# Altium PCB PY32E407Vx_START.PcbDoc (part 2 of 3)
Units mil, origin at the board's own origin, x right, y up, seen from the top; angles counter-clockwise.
Board outline 5249.65 x 2929.09 mil, 4 copper layers (Top Layer, GND, POWER, Bottom Layer); 239 components, 235 nets, 934 pads, 637 vias.
Unrouted connection lines stored in the file: 84.
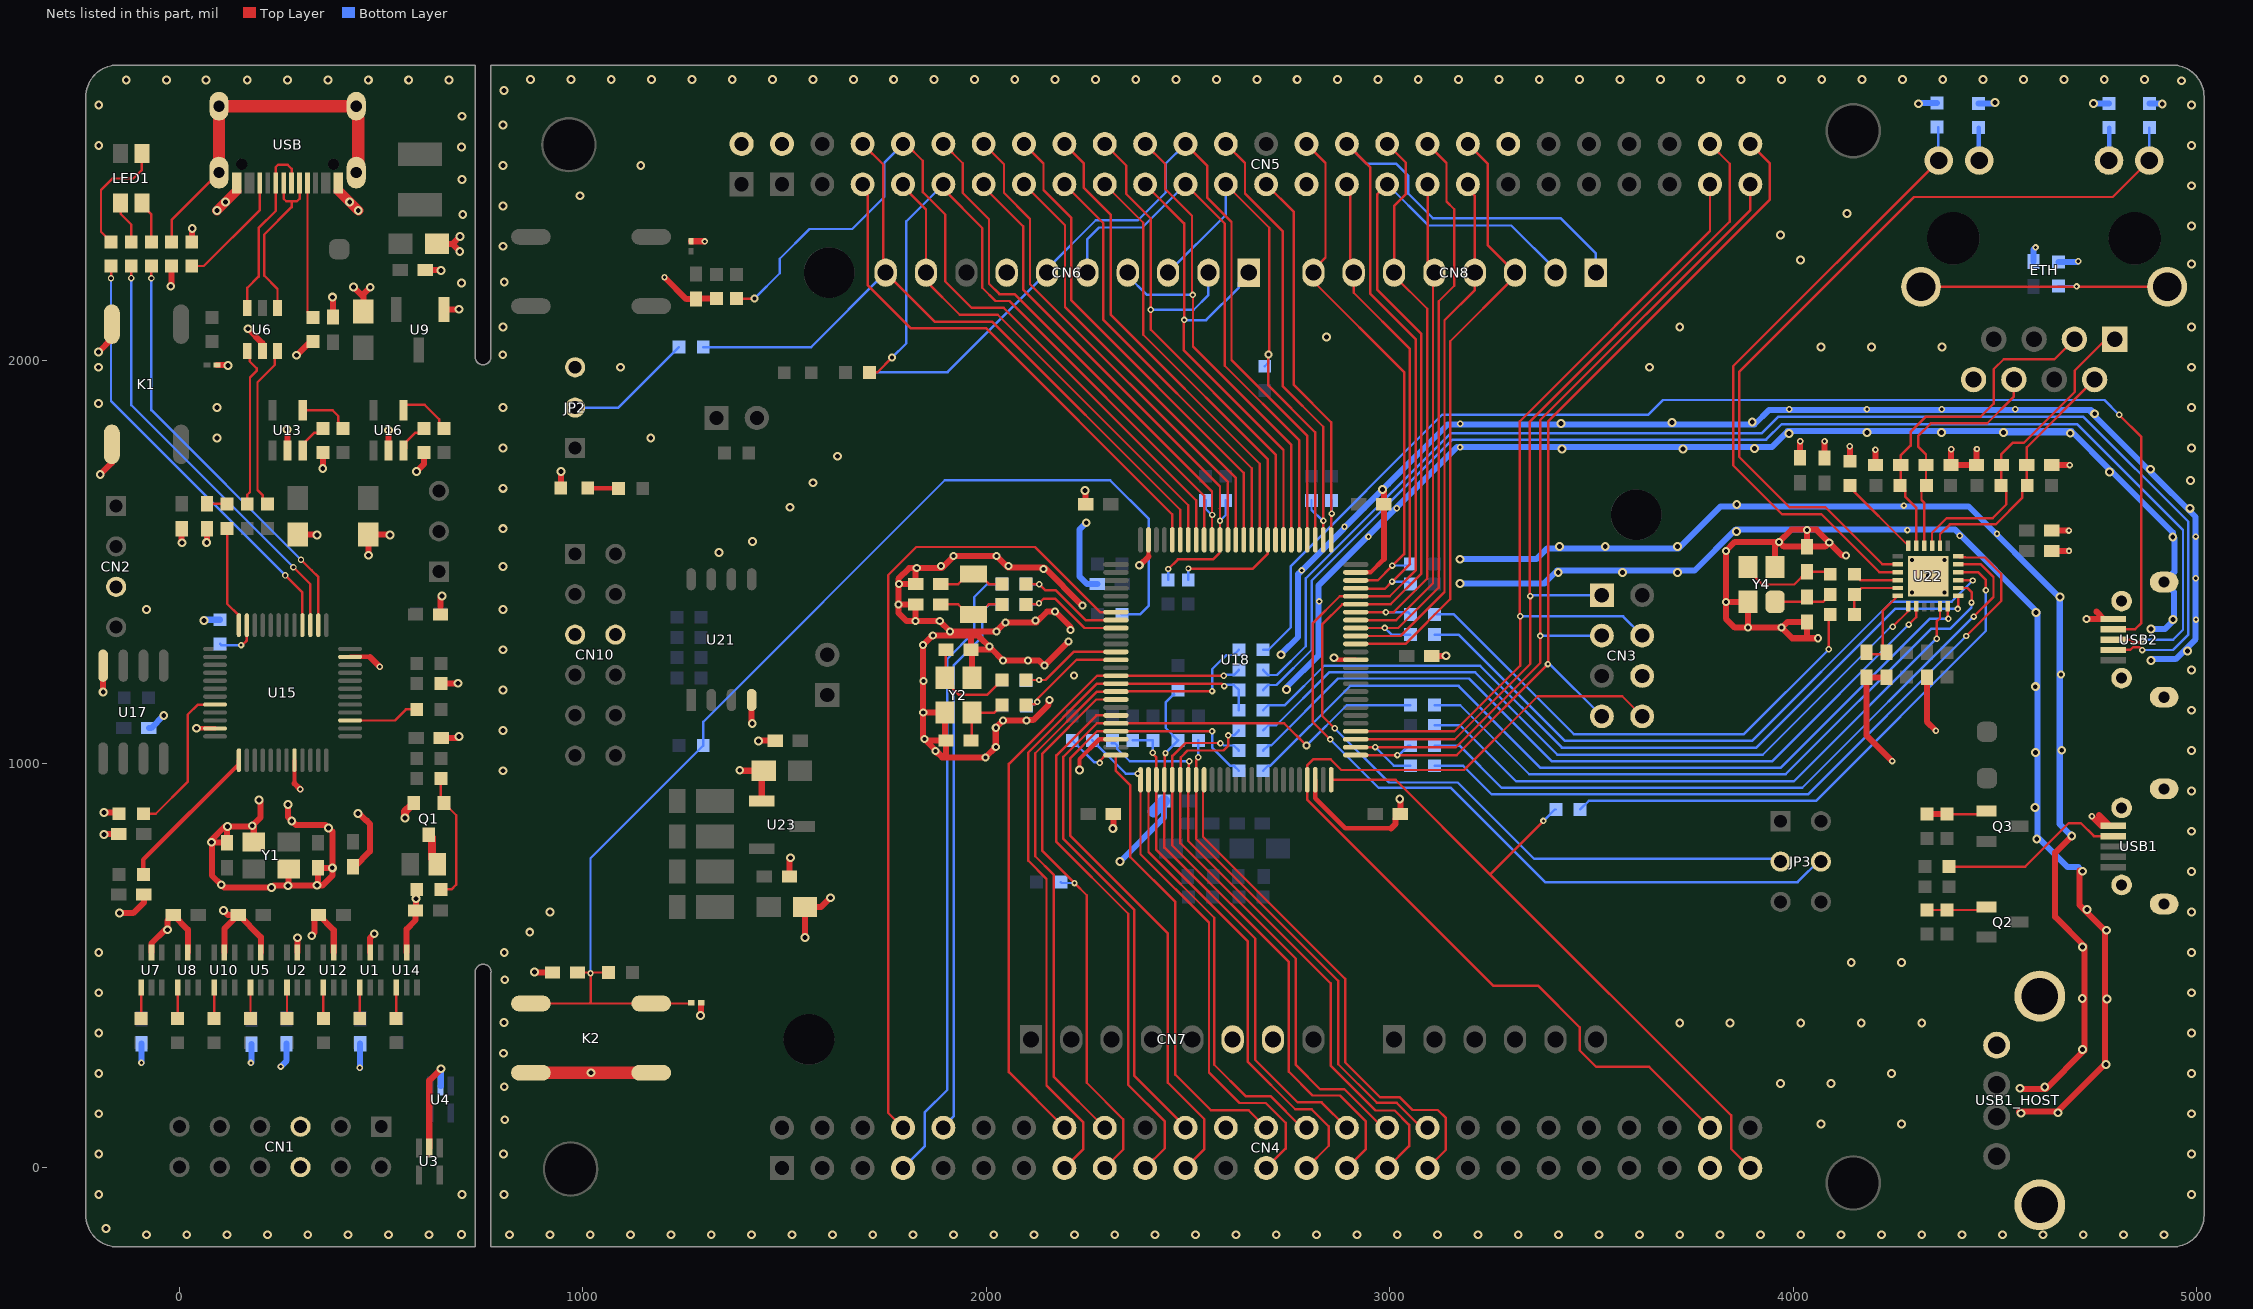
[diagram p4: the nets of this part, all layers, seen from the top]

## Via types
v1: diameter 22, hole 12, Top Layer to Bottom Layer, tented both sides, 398 vias
v2: diameter 16, hole 8, Top Layer to Bottom Layer, tented both sides, 111 vias
v3: diameter 20, hole 10, Top Layer to Bottom Layer, tented both sides, 54 vias
v4: diameter 16, hole 9, Top Layer to Bottom Layer, tented both sides, 41 vias
v5: diameter 30, hole 15, Top Layer to Bottom Layer, tented both sides, 15 vias
v6: diameter 20, hole 10, Top Layer to Bottom Layer, 9 vias
v7: diameter 15, hole 8, Top Layer to Bottom Layer, tented both sides, 5 vias
v8: diameter 16, hole 8, Top Layer to Bottom Layer, 3 vias
v9: diameter 20, hole 12, Top Layer to Bottom Layer, tented both sides, 1 vias

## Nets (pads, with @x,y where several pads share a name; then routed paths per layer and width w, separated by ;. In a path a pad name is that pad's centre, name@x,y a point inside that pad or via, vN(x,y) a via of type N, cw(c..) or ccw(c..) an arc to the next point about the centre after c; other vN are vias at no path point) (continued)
GND: C1.1 C2.1 C3.1 C4.1 C5.1 C6.1 C7.1 C8.1 C9.1 C10.1 C11.1 C12.1 C13.1 C14.1 C15.1 C16.1 C17.1 C18.1 C19.1 C20.1 C21.1 C22.1 C23.1 C24.1 C25.1 C26.1 C27.1 C28.1 C29.1 C30.1 C31.1 C32.1 C33.1 C34.1 C39.1 C40.1 C41.1 C42.1 C43.1 C44.1 C45.1 C46.1 C47.1 C48.1 C49.1 C50.2 C51.1 C52.1 C53.1 C54.1 C55.1 C56.1 C57.1 C58.1 CN1.5 CN1.6 CN2.3 CN3.6 CN4.24 CN4.47 CN5.2 CN5.27 CN5.38 CN6.7 CN7.6 CN7.7 CN10.5 CN10.6 CN11.2 ETH.8 JP2.3 K1.1 K2.2 L4.1 LED3.2 Q1.2 R1.1 R3.2 R7.2 R19.1 R20.1 R25.1 R27.2 R29.1 R32.2 R78.2 R82.1 R102.2 R103.1 R104.1 R106.1 R109.1 U1.2 U2.2 U3.2 U4.2 U5.2 U6.2 U7.2 U8.2 U9.1 U10.2 U11.2 U12.2 U13.2 U14.2 U15.8 U15.23 U15.47 U16.2 U17.4 U18.23 U18.48 U18.63 U18.74 U18.99 U19.2 U20.2 U21.4 U22.25 U23.1 USB1.5 USB1.6 USB1.7 USB1.8 USB1.9 USB1_HOST.4 USB1_HOST.5 USB2.5 USB2.6 USB2.7 USB2.8 USB2.9 USB.A1 USB.A12 USB.B1 USB.B12 Y1.2 Y1.4 Y2.2 Y2.4 Y4.2 Y4.4 | length 25027.6
  Top Layer w11: v1@42.64,1087.25 U15.47@88.04,1087.25 ; 285.03,950.62 U15.8@285.03,1008.18 ; U15.23@422.82,1264.27 472.02,1264.27 ; v1(2230.48,983.64) 2230.48,1011.16 2279.56,1060.24 U18.23@2320.76,1060.24 ; 2401.46,1512.92 U18.99@2401.46,1554.33 ; U18.48@2814.85,959.85 2814.85,913.94 2889.41,839.39 3002.73,839.39 ; v1(2860.83,1262.2) 2863.8,1262.2 2868.91,1257.09 U18.63@2915.24,1257.09 ; U18.74@2915.24,1473.63 2951.64,1473.63 2984.6,1506.59
  Top Layer w15: v1(-200.6,2020) -167.7,2052.9 K1.1@-167.7,2089 ; v1(-196.4,1716.6) -167.7,1745.3 K1.1@-167.7,1791 ; U17.4@-189.3,1242.5 -189.3,1177.2 v1(-189.1,1177) ; v1(-187.5,824.4) -186.4,825.5 C22.1@-150.5,825.5 ; v1(-186.8,879.1) -153.1,879.1 R27.2@-149.5,875.5 ; v1(-148.9,629.19) -114.8,629.19 -88.5,655.49 C20.1@-88.5,675.5 ; U7.2@-69.37,531.35 -69.37,554.39 -35.78,587.99 v1(-30,587.99) -30,610.6 C9.1@-15.7,624.9 20.97,588.23 U8.2@20.97,531.35 ; v1(-21.5,2182.89) -19.5,2184.89 R7.2@-19.5,2233 ; C5.1@5.5,1582 5.5,1548.19 v1(6.5,1547.19) ; R3.2@30.5,2293 30.5,2325.09 v1(31.6,2326.19) ; v1(42.5,1087.39) v1@42.64,1087.25 ; v1(67.41,1548.02) 68,1548.62 C16.1@68,1582 ; v1(79.73,804.88) 78.34,806.27 78.34,809.58 112.86,844.09 v1(119,844.09) 180,844.09 180.31,844.41 v1(180.31,845.73) 201.11,866.53 ; U11.2@92.8,1988 118.8,1988 v1(119.9,1986.9) ; v1(109.46,635.54) 120.09,624.9 C7.1@145.6,624.9 ; U10.2@111.31,531.35 111.31,590.61 C7.1@145.6,624.9 ; v1@118,843.09 C18.1@118,803.6 116.72,804.88 80.6,804.88 80.6,722.34 v1(103.41,699.53) 110.12,692.82 v1(228,692.82) 233.02,697.85 v1@340.42,697.85 ; USB.A12@141.34,2424.38 USB.A12@141.34,2454.43 ; v1(169.57,2077.44) 169.86,2077.44 205.5,2041.81 U6.2@205.5,2022.35 ; Y1.2@183.99,806.07 v1@183.99,842.05 ; v1(196.93,909.29) 200.79,905.43 200.79,866.85 ; U5.2@201.66,531.35 201.66,569.94 146.7,624.9 C7.1@145.6,624.9 ; v1(266.8,1827.9) 268,1826.7 U13.2@268,1775.5 ; v1(269.05,898.67) v1@269.3,898.92 ; v1@269.3,898.67 269.3,867.02 288.22,848.09 361.61,848.09 378.78,830.92 v1(378.78,741.6) ; v1@270.61,698.7 Y1.4@270.61,739.14 ; 285.03,950.62 v4(299.69,935.96) ; v1(290.2,2012) 323.7,2045.5 R1.1@330.5,2045.5 ; U2.2@292,531.35 292.07,531.42 292.07,567.82 v1(292.43,568.19) ; C6.1@293,1568 339.4,1568 v1(340.6,1566.8) ; v1(327.92,573.23) 327.92,575.12 334.56,581.76 334.56,622.22 337.24,624.9 C10.1@344.5,624.9 382.34,587.06 U12.2@382.34,531.35 ; v1(340.97,698.4) 354.87,698.4 378.78,722.31 v1(378.78,741.6) ; v1@343,700.43 C23.1@343,741.6 v1(378.78,741.6) ; v1(355.1,1731.5) 355.5,1731.9 R25.1@355.5,1770.5 ; v1(379.4,2155.8) 380.5,2154.7 C2.1@380.5,2106.5 ; USB.A1@394.32,2423.59 USB.A1@394.32,2454.49 ; C21.1@430.5,744.5 434.17,744.5 471.88,782.21 471.88,850.71 464.1,858.49 463.14,858.49 445.76,875.87 v1(442.78,875.87) ; v1(430.9,2181.4) 455.5,2156.8 ; C1.1@455.5,2120.5 455.5,2156.8 ; v1(468.62,1516.3) 468,1516.92 C15.1@468,1568 519.89,1568 v1(521.6,1566.29) ; 472.02,1264.27 v4(496.57,1239.72) ; U1.2@472.69,531.35 472.69,568.03 v1(482.82,578.16) ; v1(472.7,2180.4) 455.5,2163.2 455.5,2156.8 ; v1(517.6,1825.9) 518,1825.5 U16.2@518,1775.5 ; U14.2@563.03,531.35 563.03,589.77 585,611.74 C8.1@585,636.09 586,637.09 v1(586,665.09) 588,667.09 R19.1@588,688 ; Q1.2@573.6,895.37 Q1.2@580.6,902.37 ; v1(587.6,1723.94) 605.5,1741.84 R29.1@605.5,1770.5 ; C4.1@609.1,2223.2 646.7,2223.2 v1(647.8,2222.1) ; U3.2@619,47.46 619,214.18 v1(648.39,243.57) ; C3.1@638,2288 675.69,2288 ; C19.1@647,1369.3 647,1411.19 v1(650.8,1414.99) ; R20.1@648,1198 688.91,1198 v1(690,1199.09) ; C24.1@649,1063 689.21,1063 v1(693.1,1066.89) ; U9.1@655.5,2125.5 692.01,2125.5 v1(692.4,2125.89) ; v1(694.5,2269.19) 675.69,2288 ; v1(694.9,2306.09) 676.81,2288 675.69,2288 ; v1(879.9,482.99) 880.8,482.09 C29.1@924.5,482.09 ; LED3.2@945,1683.09 945,1723.19 v1(945.5,1723.69) ; v2(1202,2205.09) 1256,2151.09 C39.1@1280.5,2151.09 1281.5,2152.09 R82.1@1330.5,2152.09 ; U20.2@1268,2294.4 1301.1,2294.4 v2(1301.55,2293.94) ; v1(1291.5,375.24) 1292.8,376.54 U19.2@1292.8,407.09 ; v1(1388.5,983.39) 1389.8,982.09 C55.1@1448,982.09 1443,977.09 U23.1@1443,907.09 ; U21.4@1418,1157.49 1418,1100.59 v1(1419.4,1099.19) ; v1(1434.7,1055.49) 1435.8,1056.59 C56.1@1476.4,1056.59 ; C57.1@1511.6,720.29 1511.6,763.79 v1(1514.4,766.59) ; v1(1550.34,569.03) 1550.5,569.19 C54.1@1550.5,644.59 1590.3,644.59 v1(1613.21,667.51) ; v3@1781.7,1395.19 v3(1782.3,1394.59) C28.1@1824.5,1394.59 v3(1824.5,1353.19) v3@1824.6,1353.09 ; v3(1782.7,1444.59) C27.1@1824.5,1444.59 1824.5,1481.79 v3(1827.2,1484.49) ; v3(1843.29,1126.28) Y2.4@1897.03,1126.28 1897.03,1057.09 v3@1849.7,1057.09 ; v3(1873.6,1030.69) 1879.11,1025.19 1880.26,1025.19 1890.15,1015.29 1891.5,1015.29 ; C26.1@1899.5,1057.09 1899.5,1015.79 1900,1015.29 ; 1961.5,1316.59 C25.1@1961.5,1282.09 ; Y2.2@1963.96,1212.9 1963.96,1279.63 C25.1@1961.5,1282.09 ; v3(2007,1290.49) 2007,1289.59 v3@2012.8,1283.79 ; v3@2098.7,1106.39 v3(2040.7,1106.39) v3(2023,1088.69) v3(2023,1040.79) v3(1997.5,1015.29) 1891.5,1015.29 ; v3@2099.68,1107.78 2115.68,1107.78 2153.78,1145.88 2153.78,1154.94 v3(2156.6,1157.76) v3@2158.2,1157.76 ; v3(2203.4,1302.59) v3(2143.3,1242.49) 2129.9,1255.89 v3(2102.4,1255.89) v3(2040.7,1255.89) v3@2012.8,1283.79 ; v3(2208.6,1331.19) 2208.6,1338.49 v3(2170.2,1376.89) 2150.4,1376.89 2123.35,1349.85 v3(2046.85,1349.85) v3(2024.7,1327.69) v3(1909.6,1327.69) v3(1884.2,1353.09) v3@1824.6,1353.09 ; v3(2237.6,1391.29) 2142.7,1486.19 2053,1486.19 v3(2025.2,1513.99) v3(1918.38,1513.99) 1888.88,1484.49 v3(1827.2,1484.49) ; v1(2244.3,1676.89) 2245.7,1675.49 C34.1@2245.7,1642.49 ; v1(2313.1,839.19) 2314.54,840.63 C32.1@2314.54,875.01 ; v1(2378.76,1491.31) 2379.86,1491.31 2401.46,1512.92 ; v1(2981.33,1679.59) 2984.6,1676.31 C33.1@2984.6,1642.49 2984.6,1506.59 ; 3002.73,839.39 3014.15,850.81 3014.15,863.55 C31.1@3025.61,875.01 ; v1(3024.2,912.19) 3025.61,910.78 C31.1@3025.61,878.2 ; C30.1@3103.8,1266.29 3137.94,1266.29 v1(3138.8,1267.16) ; v3(3832.9,1400.79) Y4.4@3887.53,1400.79 3887.53,1337.13 v3(3887.1,1336.7) ; Y4.2@3954.46,1487.4 3954.46,1539.36 v3(3964.41,1549.3) ; C48.1@4016.2,1757.89 4016.2,1798.49 v2(4016.7,1798.99) ; 4033.5,1315.04 C51.1@4033.5,1350.59 3984.59,1350.59 v3(3970.7,1336.7) ; v3(4033.5,1578.79) C50.2@4033.5,1537.59 ; v3(4061,1310.49) 3996.9,1310.49 v3(3970.7,1336.7) ; C47.1@4076.7,1757.19 4076.7,1798.29 v2(4076.9,1798.49) ; v3(4088.65,1547.64) 4078.6,1537.59 C50.2@4033.5,1537.59 ; v3(4130.2,1515.39) 4120.9,1515.39 4056.4,1579.89 3995,1579.89 v3(3964.41,1549.3) ; v2(4139.5,1786.29) 4139.7,1786.09 R102.2@4139.7,1749.09 ; v2(4203.1,1777.59) 4203.4,1777.29 C41.1@4203.4,1739.59 ; C53.1@4230.5,1213.59 C52.1@4180.5,1213.59 4180.5,1070.09 v2(4244.5,1006.09) ; C49.1@4330.5,1213.59 4330.5,1103.79 v2(4353.1,1081.19) ; v2(4391.2,1778.89) 4390.4,1778.09 C42.1@4390.4,1739.59 C43.1@4453.4,1739.59 4453.4,1778.39 v2(4454.5,1779.49) ; v1@4558.7,137.29 4654.1,137.29 4771.91,255.1 4771.91,586.39 4709.26,649.04 4709.26,734.45 4714.88,734.45 v1(4716.11,733.22) ; v1@4560.6,193.19 4625.05,193.19 4720.9,289.05 4720.9,547.89 4648.6,620.19 4648.6,779.13 v1(4689.69,820.22) ; C45.1@4640,1527.09 4682.58,1527.09 v2(4682.74,1526.86) v2(4682.74,1526.86) ; C46.1@4640,1577.09 4682.44,1577.09 v2(4682.72,1577.37) ; C44.1@4640.4,1739.59 4640.5,1739.69 v2(4684.5,1739.69) ; v6(4726,1357.99) 4726.12,1357.99 4726.4,1358.27 USB2.5@4792.65,1358.27 4769.02,1358.27 4751.15,1376.15 ; v2(4739.5,869.39) 4763.12,845.77 USB1.5@4783.82,845.77 ; 4757.6,871.99 USB1.5@4783.82,845.77 ; USB1.5@4792.65,845.77 USB1.5@4783.82,845.77 ; v3@1824.6,1353.09 1802.3,1353.09 1781.7,1373.69 1781.7,1457.79 1808.4,1484.49 v3(1827.2,1484.49) ; v3@1849.7,1057.09 1843,1063.79 v3(1843,1293.89) v3(1866.9,1317.79) 1978.8,1317.79 v3@2012.8,1283.79 ; v3@1849.7,1057.09 1891.5,1015.29 ; C25.1@1961.5,1282.09 2011.1,1282.09 v3@2012.8,1283.79 ; v3(3964.41,1549.3) 3976.12,1537.59 C50.2@4033.5,1537.59 ; v3(3964.41,1549.3) 3854.89,1549.3 v3(3832.39,1526.8) 3832.39,1359.01 3854.7,1336.7 v3(3970.7,1336.7)
  Top Layer w20: v1(559.11,864.91) 559.11,880.88 Q1.2@573.6,895.37
  Top Layer w25: v1(92.86,2370.4) v1(114.23,2391.77) USB.A12@141.38,2418.92 ; USB.A1@394.62,2418.92 v1(421.77,2391.77) v1(443.14,2370.4)
  Top Layer w30: K2.2@871,233.59 K2.2@1169,233.59
  Bottom Layer w15: C12.1@-94.3,305.6 v2(-94.3,258.39) v2@-94,258.09 ; C17.1@-76,1088 -70.1,1088 v1(-38.9,1119.2) ; v1(61.1,1354.39) 63.1,1356.39 R32.2@100.8,1356.39 ; v2(177,258.09) 178.2,259.29 C13.1@178.2,304.3 ; v2(251,249.09) 265.7,263.79 C11.1@265.7,305.7 ; v2(447,246.09) 447.9,246.99 C14.1@447.9,305.7 ; U4.2@647,200.46 647.7,201.16 647.7,242.87 v1(648.39,243.57) ; v1(2247.1,1596.79) 2230.1,1579.79 2230.1,1464.19 2249.7,1444.59 C58.1@2274.5,1444.59 ; v1(2330.8,756.95) 2440.4,866.55 R78.2@2440.4,907.19 ; v1(2730.3,1269.49) 2730.3,1271.79 2772.11,1313.6 2772.11,1469.41 2774.8,1472.09 2996.09,1693.38 ; v1(2743.43,1183.82) 2743.43,1188.93 2823.22,1268.72 2823.22,1441.62 3166.55,1784.95 3946.85,1784.95 3985.62,1823.71 v1@4688.98,1823.71 ; v1(2981.33,1679.59) 2982.29,1679.59 2996.09,1693.38 ; v1(3173.2,1446.49) 3382.5,1446.49 3414.5,1478.49 3755,1478.49 3857,1580.49 4399.6,1580.49 v1@4604.5,1375.59 ; v1(3173.2,1506.39) 3362.61,1506.39 3389.01,1532.79 3714.9,1532.79 3819.3,1637.19 4433.7,1637.19 4659.9,1410.99 4659.9,850.3 4661.37,848.83 4661.37,848.42 4689.58,820.22 v1(4689.69,820.22) 4686.88,823.03 v1@4686.88,824.84 ; v1(4309.48,2635.12) 4311.46,2637.09 R104.1@4355.5,2637.09 ; R106.1@4459,2636.09 4497.36,2636.09 v1(4499.61,2638.34) ; v1(4520.38,1820.15) 4685.42,1820.15 v1@4688.98,1823.71 ; C40.1@4594.5,2244.09 4594.5,2273.59 v2(4600,2279.09) ; v1(4600.86,1374.3) 4603.2,1374.3 v1@4604.5,1375.59 ; L4.1@4657,2243.09 4704,2243.09 v2(4705.5,2244.59) ; v1(4716.11,733.22) 4706.08,743.25 4679.74,743.25 4604.5,818.49 4604.5,890.77 4604.5,1032.22 4604.5,1190.49 v1@4604.5,1375.59 ; v1(4743.69,2636.07) R109.1@4782,2636.09 ; v1(4746.43,1866.91) 4736.63,1876.71 4731.08,1876.71 ; v1(4783.11,1722.47) 4789.94,1722.47 4939.87,1572.55 v1(4939.87,1561.82) 4943.3,1558.38 4943.7,1558.38 4943.7,1475.15 USB2.7@4918.35,1449.8 4942.78,1425.37 4942.78,1359.02 v1(4940.65,1356.89) ; v1@4786.67,1726.03 v1@4688.98,1823.71 ; R103.1@4882,2636.09 4912.44,2636.09 v1(4913.76,2634.78) ; v1(4884.42,1729.44) 4884.42,1723.37 4996.8,1610.99 ; v1(4886.1,1255.3) 4889.43,1258.64 4947.18,1258.64 4996.8,1308.26 4996.8,1610.99 ; v1@4888.51,1330.89 v1(4886.1,1333.29) 4920.41,1333.29 v1@4940.65,1353.53 ; 2996.09,1693.38 3143.03,1840.33 3903.43,1840.33 3939.82,1876.71 4731.08,1876.71 ; 4731.08,1876.71 4996.8,1610.99
  Bottom Layer w30: 2414.4,881.19 R78.2@2440.4,907.19
  other v1: -82,-167.91 18,-167.91 118,-167.91 218,-167.91 318,-167.91 418,-167.91 518,-167.91 618,-167.91 818,-167.91 918,-167.91 1018,-167.91 1118,-167.91 1218,-167.91 1318,-167.91 1418,-167.91 1518,-167.91 1618,-167.91 1718,-167.91 1818,-167.91 1918,-167.91 2018,-167.91 2118,-167.91 2218,-167.91 2318,-167.91 2418,-167.91 2518,-167.91 2618,-167.91 2718,-167.91 2818,-167.91 2918,-167.91 3018,-167.91 3118,-167.91 3218,-167.91 3318,-167.91 3418,-167.91 3518,-167.91 3618,-167.91 3718,-167.91 3818,-167.91 3918,-167.91 4018,-167.91 4118,-167.91 4218,-167.91 4318,-167.91 4418,-167.91 4518,-167.91 4618,-167.91 4718,-167.91 4818,-167.91 4918,-167.91 699,-166.91 -182,-151.91 -200,-67.91 700,-67.91 804,-67.91 4986,-67.91 -200,32.09 803,32.09 4986,32.09 4068,107.09 4268,107.09 806,117.09 -200,132.09 4986,132.09 4564.07,133.4 4655.66,134.66 4561.61,195.4 4622.77,198.53 805,199.09 3968,207.09 4093,207.09 -200,232.09 4243,232.09 4986,232.09 1020,233.59 4774.65,253.93 803,282.09 4715.92,291.09 -200,332.09 4986,332.09 3718,357.09 3843,357.09 4018,357.09 4168,357.09 4318,357.09 804,358.09 4777.1,416.27 4715.62,417.47 -200,432.09 4986,432.09 806,464.09 4143,507.09 4268,507.09 -200,532.09 805,532.09 4986,532.09 4715.94,545.57 868,582.09 4775.74,586.97 918,632.09 4986,632.09 4727.01,638.57 269,697.09 4986,732.09 4602.84,813.23 4986,832.09 369.17,840.53 278.29,858.03 4598.86,890.77 4986,932.09 802,982.09 4600,1027.09 4986,1032.09 4664.91,1033.05 802,1082.09 4986,1132.09 802,1182.09 4599.3,1190.49 4986,1232.09 4976.16,1279.08 802,1282.09 -82,1382.09 802,1382.09 4660.78,1412.8 3417.12,1473.15 3576.08,1473.33 3712.6,1473.53 802,1488.09 1336.8,1522.89 3420.44,1538.04 3533.62,1537.99 3712.45,1537.97 1420.1,1550.69 3859.03,1575.43 802,1582.09 4982.77,1632.55 1512.8,1635.09 3859.49,1641.92 802,1682.09 1570.1,1695.99 4983.9,1701.29 1630.4,1761.59 3426.61,1779.85 3726.4,1779.79 3903.69,1780.4 802,1782.09 4986,1782.09 93,1807.09 1168,1807.09 3988.62,1817.95 4685.9,1818.65 4182.4,1820.15 4366.6,1820.15 3424.17,1843.05 3698.7,1844.89 3897.7,1846.79 93,1882.09 802,1882.09 4986,1882.09 -201,1892.09 -201,1982.09 1093,1982.09 3643,1982.09 4986,1982.09 801,2013.09 4068,2032.09 4193,2032.09 4368,2032.09 2843,2057.09 802,2082.09 3718,2082.09 4986,2082.09 699,2191.09 805,2193.09 4986,2238.09 4017,2248.09 802,2282.09 3968,2310.09 4986,2332.09 702,2361.09 4133,2363.09 802,2382.09 993,2407.09 4986,2432.09 700,2447.09 802,2482.09 1143,2482.09 699,2528.09 -200,2532.09 4986,2532.09 802,2582.09 700,2604.09 -200,2632.09 4986,2632.09 804,2668.09 4962,2692.09 -132,2694.09 -32,2694.09 66,2694.09 168,2694.09 268,2694.09 368,2694.09 468,2694.09 568,2694.09 668,2694.09 870,2695.09 970,2695.09 1070,2695.09 1170,2695.09 1270,2695.09 1370,2695.09 1470,2695.09 1570,2695.09 1670,2695.09 1770,2695.09 1870,2695.09 1970,2695.09 2070,2695.09 2170,2695.09 2270,2695.09 2370,2695.09 2470,2695.09 2570,2695.09 2670,2695.09 2770,2695.09 2870,2695.09 2970,2695.09 3070,2695.09 3170,2695.09 3270,2695.09 3370,2695.09 3470,2695.09 3570,2695.09 3670,2695.09 3770,2695.09 3870,2695.09 3970,2695.09 4070,2695.09 4170,2695.09 4270,2695.09 4370,2695.09 4470,2695.09 4570,2695.09 4670,2695.09 4770,2695.09 4870,2695.09
  other v2: 2824.77,1401.74 2781.04,1478.69 2946.41,1562.33 4412.1,1564.79 4504.4,1569.69 4282.3,1578.59 2887.21,1586.96 3016.87,1632.8 4273.8,1639.19 3173.63,1783.63 3174.39,1841.92 4182,1877.79 4549.5,1877.79 3989.3,1878.09 4367.6,1877.99
  other v3: 1846.35,1060.44 2098.7,1106.79 1843.4,1204.29 2216.94,1217.83 4663.4,1221.19 2121.18,1354.21 4293.3,1424.29 4373.7,1424.29 2140.92,1481.84 1886.81,1489.23 2054.82,1490.11
  other v6: 4333.1,1465.49 4293.3,1504.69 4373.7,1504.69
  other v8: 4997.55,1356.78 4997.17,1459.31 4997,1562.49
L_USB_CN_DM: U6.4 USB.A7 USB.B7 | length 429.3
  Top Layer w6: U6.4@242.9,2128.65 242.9,2176.2 210,2209.1 210,2311.09 277.85,2378.94 277.85,2393.5 ; USB.A7@258.16,2438.92 258.16,2399.87 264.53,2393.5 277.85,2393.5 ; USB.B7@297.53,2438.92 297.53,2399.87 291.16,2393.5 277.85,2393.5
L_USB_CN_DP: U6.6 USB.A6 USB.B6 | length 459.8
  Top Layer w6: U6.6@168.1,2128.65 168.1,2178.79 196,2206.69 196,2327.24 238.47,2369.71 USB.B6@238.47,2438.92 238.47,2478.14 244.33,2484 268,2484 277.84,2474.16 USB.A6@277.84,2438.92
LAN8720_CRS_DV: R58.1 U22.11 | length 1531.5
  Top Layer w6: v2(4354.82,1309.49) 4354.82,1351.91 4363.03,1360.12 U22.11@4363.03,1389.49
  Bottom Layer w6: R58.1@3110.5,1094.59 3174.1,1094.59 3312.59,956.1 4000.92,956.1 4354.31,1309.49 v2(4354.82,1309.49)
LAN8720_ETH_LINK: ETH.12 R104.2 U22.3 | length 1567
  Top Layer w6: U22.3@4258.4,1474.43 4212.46,1474.43 4069.1,1617.79 3971.7,1617.79 3850.7,1738.79 3850.7,1985.08 ETH.12@4360.17,2494.55
  Bottom Layer w6: R104.2@4359,2577.09 4359,2495.72 ETH.12@4360.17,2494.55
LAN8720_ETH_RXN: C42.2 ETH.6 R99.1 U22.22 | length 608.1
  Top Layer w6: U22.22@4323.66,1539.69 4323.66,1646.73 4317.21,1653.18 4317.21,1677.41 R99.1@4329.4,1689.59 4328.4,1690.59 C42.2@4328.4,1739.59 4328.4,1766.04 4308.99,1785.45 4308.99,1811.69 4340.67,1843.36 4480.27,1843.36 4546.19,1909.29 ETH.6@4546.19,1951.64
LAN8720_ETH_RXP: C41.2 ETH.3 R98.1 U22.23 | length 860.2
  Top Layer w6: U22.23@4303.97,1539.69 4303.97,1634.42 4276.54,1661.86 4276.54,1677.46 R98.1@4264.4,1689.59 4265.4,1690.59 C41.2@4265.4,1739.59 4265.4,1763.09 4290.2,1787.89 4290.2,1821.23 4328.69,1859.72 4464.23,1859.72 4496.46,1891.95 4496.46,1977.55 4521,2002.09 4646.65,2002.09 ETH.3@4696.19,2051.64
LAN8720_ETH_SPD: ETH.9 R103.2 U22.2 | length 2029
  Top Layer w6: U22.2@4258.4,1494.12 4219.87,1494.12 4078.9,1635.09 3990.2,1635.09 3865.1,1760.19 3865.1,1970.19 4299,2404.09 4791.37,2404.09 ETH.9@4881.83,2494.55
  Bottom Layer w6: ETH.9@4881.83,2494.55 4881.83,2575.92 R103.2@4882,2576.09
LAN8720_ETH_TXN: C44.2 ETH.2 R101.1 U22.20 | length 638
  Top Layer w6: U22.20@4363.03,1539.69 4363.03,1568.12 4387.69,1592.79 4501.29,1592.79 4566.64,1658.13 4566.64,1676.83 R101.1@4579.4,1689.59 4578.4,1690.59 C44.2@4578.4,1739.59 4578.4,1783.84 ETH.2@4746.19,1951.64
LAN8720_ETH_TXP: C43.2 ETH.1 R100.1 U22.21 | length 805.9
  Top Layer w6: U22.21@4343.34,1539.69 4343.34,1571.96 4379.81,1608.43 4493.64,1608.43 4527.43,1642.22 4527.43,1676.56 R100.1@4514.4,1689.59 4515.4,1690.59 C43.2@4515.4,1739.59 4515.4,1767.11 4542.87,1794.58 4570.48,1794.58 4696.95,1921.05 4696.95,1974.05 4774.55,2051.64 ETH.1@4796.2,2051.64
LAN8720_MCO: R69.1 R108.2 | length 1275.9
  Top Layer w6: v2(4087.62,1283.38) 4087.77,1283.54 4087.77,1362.17 4085.92,1364.02 R108.2@4091,1369.09
  Bottom Layer w6: R69.1@3110.5,1369.59 3158.7,1369.59 3455.5,1072.79 3877.03,1072.79 v2(4087.62,1283.38)
LAN8720_MDC: R61.1 U22.13 | length 2026.4
  Top Layer w6: v2(4407.1,1383.16) 4408.6,1384.66 U22.13@4408.6,1415.38
  Bottom Layer w6: R61.1@2685.5,1132.09 2698.28,1144.88 2739.62,1144.88 2836.94,1242.2 3223.29,1242.2 3426,1039.49 3908.2,1039.49 4251.86,1383.16 v2(4407.1,1383.16)
LAN8720_MDIO: R66.1 U22.12 | length 2054
  Top Layer w6: U22.12@4382.71,1389.49 4382.71,1360.35 v2(4383.95,1359.11)
  Bottom Layer w6: R66.1@2685.5,982.09 2698.44,995.03 2703.8,995.03 2901.38,1192.61 3169.98,1192.61 3373.4,989.19 3968.1,989.19 4338.01,1359.11 v2(4383.95,1359.11)
LAN8720_nINT: R67.1 U22.14 | length 1648.2
  Top Layer w6: U22.14@4408.6,1435.06 4431.03,1435.06 4442,1424.09 4442,1399.84 v2(4441.13,1398.97)
  Bottom Layer w6: R67.1@3110.5,1144.59 3174.1,1144.59 3345.2,973.49 3980.5,973.49 4340.86,1333.85 4387.96,1333.85 4441.13,1387.02 v2(4441.13,1398.97)
LAN8720_nRST: R68.1 U22.15 | length 1642.9
  Top Layer w6: U22.15@4408.6,1454.75 4443.15,1454.75 v2(4444.23,1453.67)
  Bottom Layer w6: R68.1@3110.5,1319.59 3170,1319.59 3432.58,1057.01 3898.22,1057.01 4242.33,1401.13 4391.69,1401.13 v2(4444.23,1453.67)
LAN8720_RXD0: R59.1 U22.8 | length 1952.4
  Top Layer w6: v2(4285.7,1344.39) 4303.97,1362.66 U22.8@4303.97,1389.49
  Bottom Layer w6: R59.1@2685.5,1032.09 2698.5,1045.09 2705.76,1045.09 2871.42,1210.76 3196.04,1210.76 3401.4,1005.39 3946.7,1005.39 v2(4285.7,1344.39)
LAN8720_RXD1: R60.1 U22.7 | length 1902
  Top Layer w6: v2(4245.8,1338.99) 4284.29,1377.48 U22.7@4284.29,1389.49
  Bottom Layer w6: R60.1@2685.5,1082.09 2698.21,1094.81 2718.2,1094.81 2849.14,1225.75 3211.15,1225.75 3415,1021.89 3923.8,1021.89 4240.9,1338.99 v2(4245.8,1338.99)
LAN8720_TXD0: R62.1 U22.17 | length 1774.3
  Top Layer w6: U22.17@4408.6,1494.12 4463.89,1494.12 4495.62,1462.39 4495.62,1413.08 v2(4446.65,1364.11)
  Bottom Layer w6: R62.1@3110.5,1044.59 3172.1,1044.59 3276.78,939.91 4021.55,939.91 4446.2,1364.56 v2(4446.65,1364.11)
LAN8720_TXD1: R63.1 U22.18 | length 1823.9
  Top Layer w6: U22.18@4408.6,1513.8 4411.11,1511.29 4425.47,1511.29 4426.17,1510.59 4474.54,1510.59 4515.03,1470.1 4515.03,1403.03 v2(4428.06,1316.06)
  Bottom Layer w6: R63.1@3110.5,994.59 3181.37,994.59 3252.24,923.73 4036,923.73 v2@4428.06,1315.79
LAN8720_TXEN: R64.1 U22.16 | length 1391.5
  Top Layer w6: U22.16@4408.6,1474.43 4457.18,1474.43 4476.75,1454.86 v2(4476.75,1429.3)
  Bottom Layer w6: R64.1@3471.05,886.09 3492.5,907.54 4055.65,907.54 4476.6,1328.49 4476.6,1429.15 v2(4476.75,1429.3)
LAN8720_VDDCR: C52.2 C53.2 U22.6 | length 210.3
  Top Layer w6: C52.2@4171,1270.59 4221,1270.59 4221,1377.98 U22.6@4258.4,1415.38
LAN8720_XTAL1: R107.2 R108.1 U22.5 | length 163.4
  Top Layer w6: R108.1@4151,1369.09 R107.2@4151,1419.09 ; R107.2@4152,1418.09 4168.97,1435.06 U22.5@4258.4,1435.06
LAN8720_XTAL2: R105.2 U22.4 | length 113.3
  Top Layer w6: R105.2@4151,1469.09 4165.34,1454.75 U22.4@4258.4,1454.75
LED_BLUE: R8.2 U15.28 | length 1086.6
  Top Layer w6: v4(-169.7,2202.3) -169.5,2202.5 R8.2@-169.5,2233 ; v4(262.3,1466.2) 304.71,1423.78 U15.28@304.71,1343.01
  Bottom Layer w6: v4(-169.7,2202.3) -169.7,1898.19 v4(262.3,1466.2)
LED_GREEN: R5.2 U15.26 | length 1061.3
  Top Layer w6: v4(-69.5,2202.85) R5.2@-69.5,2233 ; v4(301.2,1505.1) 327.64,1478.66 344.08,1462.22 U15.26@344.08,1343.01
  Bottom Layer w6: v4(-69.5,2202.85) -69.5,1875.79 v4(301.2,1505.1)
LED_RED: R4.2 U15.27 | length 1073.9
  Top Layer w6: v4(-119.5,2203.2) R4.2@-119.5,2233 ; v4(282.5,1486.4) 324.4,1444.5 U15.27@324.4,1343.01
  Bottom Layer w6: v4(-119.5,2203.2) -119.5,1888.39 v4(282.5,1486.4)
NetC16_2: C16.2 R30.2 | length 50.4
  Top Layer w6: C16.2@68,1644 117,1644 R30.2@118,1643
NetC50_1: C50.1 R105.1 Y4.3 | length 242.2
  Top Layer w6: Y4.3@3887.53,1487.4 3887.53,1479.22 3922.93,1443.83 4001.74,1443.83 C50.1@4033.5,1475.59 4084.5,1475.59 R105.1@4091,1469.09
NetC51_2: C51.2 R107.1 Y4.1 | length 144.1
  Top Layer w6: Y4.1@3954.46,1400.79 4072.69,1400.79 R107.1@4091,1419.09
NetETH_10: ETH.10 R109.2 | length 81.6
  Bottom Layer w11: ETH.10@4781.83,2494.55 4782,2494.72 R109.2@4782,2576.09
NetETH_11: ETH.11 R106.2 | length 82
  Bottom Layer w11: R106.2@4459,2576.09 4459,2495.72 ETH.11@4460.17,2494.55
NetETH_SH1: ETH.SH1 ETH.SH2 L4.2 | length 655.5
  Top Layer w6: ETH.SH2@4316.08,2181.56 4700.93,2181.56 v2(4701.7,2182.33) 4702.46,2181.56 ETH.SH1@4925.92,2181.56
  Bottom Layer w6: L4.2@4657,2183.09 4700.93,2183.09 v2(4701.7,2182.33)
NetJP2_2: JP2.2 R65.1 | length 319.6
  Bottom Layer w6: JP2.2@980.5,1882.09 1088,1882.09 R65.1@1238,2032.09
NetLED1_2: LED1.2 R8.1 | length 301.1
  Top Layer w6: R8.1@-169.5,2293 -194.5,2318 -194.5,2421.7 -166.2,2450 -114.5,2450 -93.32,2471.19 LED1.2@-93.32,2511.52
NetLED1_3: LED1.3 R5.1 | length 106.3
  Top Layer w6: LED1.3@-93.32,2389.48 -93.32,2384.21 -69.5,2360.4 R5.1@-69.5,2293
NetLED1_4: LED1.4 R4.1 | length 107.3
  Top Layer w6: LED1.4@-145.69,2389.48 -145.69,2362.19 -119.5,2336 R4.1@-119.5,2293
NetLED3_1: LED3.1 R112.1 | length 76.4
  Top Layer w12: LED3.1@1012,1683.09 1013,1682.09 R112.1@1088,1682.09
NetQ1_1: Q1.1 R18.1 R19.2 | length 329
  Top Layer w6: R19.2@648,688 673.86,688 685.89,700.04 685.89,871.88 Q1.1@655.4,902.37 ; Q1.1@648,909.77 R18.1@648,963
  Top Layer w15: R19.2@648,688 R19.2@655.5,688 ; Q1.1@648,909.77 Q1.1@655.4,902.37
NetQ1_3: Q1.3 R15.1 | length 81.8
  Top Layer w15: Q1.3@618,823.63 Q1.3@625.29,816.34 ; R15.1@625.29,764.18 R15.1@638.96,750.5
  Top Layer w20: R15.1@625.29,764.18 Q1.3@625.29,816.34
NetQ2_1: Q2.1 R83.1 R85.2 | length 151.2
  Top Layer w6: R85.2@4330.5,637.09 R83.1@4380.5,637.09 4471.23,637.09 Q2.1@4478.63,644.49
NetQ3_1: Q3.1 R91.1 R93.2 | length 151.2
  Top Layer w6: R91.1@4380.5,874.59 4471.23,874.59 Q3.1@4478.63,881.99
  Top Layer w15: R93.2@4330.5,874.59 R91.1@4380.5,874.59
NetR1_2: R1.2 USB.A5 | length 338.9
  Top Layer w6: USB.A5@317.21,2438.92 317.21,2118.79 R1.2@330.5,2105.5
NetR2_1: R2.1 U1.4 | length 78.4
  Top Layer w6: R2.1@443,368 447.09,372.1 U1.4@447.09,444.73
NetR3_1: R3.1 USB.B5 | length 293
  Top Layer w6: R3.1@30.5,2233 59.99,2233 199.1,2372.11 USB.B5@199.1,2438.92
NetR6_1: R6.1 U2.4 | length 77.4
  Top Layer w6: U2.4@266.41,444.73 266.41,369.59 R6.1@268,368
NetR7_1: R7.1 USB.1 USB.2 USB.3 USB.4 | length 880
  Top Layer w6: R7.1@-19.5,2293 -19.5,2347.09 USB.2@97.92,2464.52
  Top Layer w30: USB.2@97.92,2464.52 USB.4@97.92,2626.13 ; USB.4@97.92,2629.08 USB.3@438.08,2629.08 ; USB.3@441.38,2624.51 441.38,2601.78 443,2600.16 443,2489.85 441.38,2488.23 441.38,2470.07 USB.1@443,2468.45
NetR9_1: R9.1 U5.4 | length 80.1
  Top Layer w6: R9.1@168,368 176.07,376.07 U5.4@176.07,444.73
NetR10_1: R10.1 U6.3 | length 410
  Top Layer w6: R10.1@218,1643 206.7,1654.3 206.7,1664.67 193.4,1677.96 193.4,1945.1 236.23,1987.93 236.23,2015.68 U6.3@242.9,2022.35
NetR11_1: R11.1 U6.1 | length 398.6
  Top Layer w6: R11.1@168,1643 168.11,1643.11 168.11,1666.31 174.8,1673 174.8,1956.48 191.25,1972.93 191.25,1979.55 174.02,1996.79 174.02,2016.43 U6.1@168.1,2022.35
NetR12_1: R12.1 U7.4 | length 76.7
  Top Layer w6: R12.1@-95,368 U7.4@-94.96,444.73 U7.4@-94.96,444.73
NetR13_1: R13.1 U8.4 | length 76.8
  Top Layer w6: R13.1@-4.71,368 -4.62,368.1 U8.4@-4.62,444.73
NetR17_1: R17.1 U10.4 | length 76.8
  Top Layer w6: R17.1@85.57,368 85.72,368.15 U10.4@85.72,444.73
NetR21_1: R21.1 U12.4 | length 77.3
  Top Layer w6: R21.1@355.5,368 356.75,369.25 U12.4@356.75,444.73
NetR23_2: R23.2 U13.4 | length 124.7
  Top Layer w6: U13.4@305.5,1875.5 379.38,1875.5 393.5,1861.38 393.5,1847.5 R23.2@405.5,1835.5
NetR24_1: R24.1 U14.4 | length 79.6
  Top Layer w6: R24.1@524.5,368 R24.1@531.44,374.94 ; R24.1@537.44,374.94 U14.4@537.44,444.73
NetR25_2: R25.2 U13.3 | length 82
  Top Layer w6: U13.3@305.5,1775.5 311.5,1781.5 311.5,1797.19 333.67,1819.36 344.36,1819.36 R25.2@355.5,1830.5
NetR26_2: R26.2 U15.1 | length 380.7
  Top Layer w11: R26.2@-89.5,725.5 -89.5,762.11 147.23,998.84 U15.1@147.23,1008.18
NetR27_1: R27.1 U15.44 | length 387.1
  Top Layer w6: R27.1@-89.5,875.5 -58.78,875.5 20.3,954.58 20.3,1120.79 45.48,1145.97 U15.44@88.18,1145.97
NetR28_2: R28.2 U16.4 | length 138.8
  Top Layer w6: U16.4@555.5,1875.5 555.5,1883.35 561.5,1889.35 607.36,1889.35 643.62,1853.09 643.62,1842.5 650.62,1835.5 R28.2@655.5,1835.5
NetR29_2: R29.2 U16.3 | length 86.5
  Top Layer w6: U16.3@555.5,1775.5 561.5,1781.5 561.5,1797.22 583.66,1819.37 593.5,1819.37 605.5,1831.37 R29.2@605.5,1835.5
NetR30_1: R30.1 U15.36 | length 252.3
  Top Layer w6: R30.1@118,1583 118,1396 147.23,1366.77 U15.36@147.23,1342.82
NetR31_2: R31.2 U15.15 | length 180.6
  Top Layer w6: U15.15@422.82,1106.6 533.67,1106.6 561.16,1134.09 R31.2@592,1134.09
NetR32_1: R32.1 U15.35 | length 110.1
  Top Layer w6: v2(152.7,1293.59) 155.41,1293.59 165.8,1303.99 166.1,1303.99 166.92,1304.81 U15.35@166.92,1343.01
  Bottom Layer w6: R32.1@100.8,1296.39 103.6,1293.59 v2(152.7,1293.59)
NetR84_2: R84.2 USB1.4 | length 464.7
  Top Layer w6: R84.2@4385.5,744.59 4574.2,744.59 4681.5,851.89 4712.6,851.89 4744.31,820.18 USB1.4@4792.65,820.18
NetR92_2: R92.2 USB2.4 | length 3096.8
  Top Layer w6: USB2.4@4792.65,1332.68 4846.59,1332.68 4862.2,1348.29 4862.2,1809.19 v2(4807.1,1864.29)
  Bottom Layer w6: R92.2@2685.5,1282.09 2698.64,1282.09 2754.42,1337.88 2754.42,1489.53 3129.6,1864.71 3640.42,1864.71 3676.6,1900.89 4770.5,1900.89 v2(4807.1,1864.29)
NetR94_2: R94.2 USB2.3 | length 3197.6
  Top Layer w6: USB2.3@4792.65,1307.09 4834.7,1307.09 4841.48,1300.32 4857.23,1300.32 v2(4864.16,1307.26)
  Bottom Layer w6: R94.2@2685.5,1182.09 2698.02,1194.61 2718.6,1194.61 2806,1282.02 2806,1453.4 3155.26,1802.65 3932.26,1802.65 3970.8,1841.19 4702.8,1841.19 4965.39,1578.61 4965.39,1331.48 4941.16,1307.26 v2(4864.16,1307.26)
NetR95_2: R95.2 USB2.2 | length 3256.3
  Top Layer w6: USB2.2@4792.65,1281.5 4834.7,1281.5 4841.48,1288.28 4857.23,1288.28 v2(4864.16,1281.34)
  Bottom Layer w6: R95.2@2685.5,1232.09 2698.06,1219.53 2720.25,1219.53 2791.3,1290.58 2791.3,1458.79 3151.27,1818.77 3921.71,1818.77 3961.94,1858.99 4718.8,1858.99 4978.51,1599.28 4978.51,1319.6 4940.25,1281.34 v2(4864.16,1281.34)
NetR102_1: R102.1 U22.24 | length 209.3
  Top Layer w6: R102.1@4139.7,1689.09 4139.7,1684.28 U22.24@4284.29,1539.69
NRST: C29.2 K2.1 R54.1 R57.2 R72.2 U19.1 | length 2962.2
  Top Layer w6: K2.1@871,405.29 1016.2,405.29 ; C29.2@986.5,482.09 1017,482.09 v2(1018.63,480.46) ; R57.2@1050.5,482.09 1020.27,482.09 v2(1018.63,480.46) ; U19.1@1269,406.29 U19.1@1268.2,407.09 1266.4,405.29 K2.1@1169,405.29 1016.2,405.29 ; 1016.2,405.29 1018.79,407.88 1018.79,480.31 v2(1018.63,480.46)
  Bottom Layer w6: v2(1018.63,480.46) 1018.63,765.23 R72.2@1298,1044.59 1298,1103.39 1896.6,1701.99 2306.38,1701.99 2402.5,1605.88 2402.5,1391.33 2380.77,1369.59 R54.1@2335.5,1369.59
OSC_32IN: C27.2 R42.1 Y3.2 | length 172.4
  Top Layer w6: C27.2@1886.5,1444.59 1930.02,1444.59 1955.21,1469.79 Y3.2@1968,1469.79 1980.8,1469.79 2005.99,1444.59 R42.1@2038,1444.59
OSC_32INa: R37.2 R42.2 U18.8 | length 292.2
  Top Layer w6: R42.2@2098,1444.59 v2(2130.5,1444.59) 2145.94,1429.16 2171.95,1429.16 2245.59,1355.52 U18.8@2320.76,1355.52
  Bottom Layer w6: R37.2@2098,1444.59 v2(2130.5,1444.59)
OSC_32OUT: C28.2 R45.1 Y3.1 | length 172.4
  Top Layer w6: C28.2@1886.5,1394.59 1930.01,1394.59 1955.21,1369.4 Y3.1@1968,1369.4 1980.57,1369.4 2005.77,1394.59 R45.1@2038,1394.59
OSC_32OUTa: R38.2 R45.2 U18.9 | length 292.2
  Top Layer w6: R45.2@2098,1394.59 2127.64,1394.59 2141.95,1408.91 2169.59,1408.91 2242.67,1335.83 U18.9@2320.76,1335.83
  Bottom Layer w6: R38.2@2098,1394.59 2127.64,1394.59 v2(2130.16,1397.11)
OSC_IN: C25.2 R36.1 Y2.3 | length 249
  Top Layer w6: C25.2@1899.5,1282.09 1899.5,1215.37 Y2.3@1897.03,1212.9 1917.66,1192.28 1917.66,1184.23 1931.87,1170.02 2000.93,1170.02 R36.1@2038,1207.09
OSC_INa: R36.2 R40.2 U18.12 | length 284.3
  Top Layer w6: R36.2@2098,1207.09 v2(2130.4,1207.09) 2146.1,1207.09 2215.78,1276.77 U18.12@2320.76,1276.77
  Bottom Layer w6: R40.2@2098.2,1205.99 2099.3,1207.09 v2(2130.4,1207.09)
OSC_OUT: C26.2 R39.1 Y2.1 | length 151.8
  Top Layer w6: C26.2@1961.5,1057.09 1963.96,1059.56 Y2.1@1963.96,1126.28 2019.69,1126.28 R39.1@2038,1144.59
OSC_OUTa: R39.2 R41.2 U18.13 | length 304.4
  Top Layer w6: R39.2@2098,1144.59 2100.31,1146.9 2120.14,1146.9 v2(2125.88,1152.65) 2125.88,1159.68 2223.3,1257.09 U18.13@2320.76,1257.09
  Bottom Layer w6: R41.2@2099.3,1142.19 2104.01,1146.9 2120.14,1146.9 v2(2125.88,1152.65)
PA0: CN4.19 U18.20 | length 1342.9
  Top Layer w6: U18.20@2320.76,1119.29 2320.7,1119.37 2272.37,1119.37 2173.21,1020.2 2173.21,805.79 2351.2,627.79 2351.2,203.69 2442,112.89 2442,46.44 CN4.19@2393.11,-2.45
PA1: CN4.22 R67.2 U18.21 | length 2003.1
  Top Layer w6: CN4.22@2493.11,97.55 2493.11,99.33 2365.8,226.64 2365.8,637.89 2190.61,813.08 2190.61,1017.01 2273.22,1099.61 U18.21@2320.76,1099.61 2737.98,1099.61 v6(2793,1044.59)
  Bottom Layer w6: v6(2793,1044.59) 2893,1144.59 R67.2@3050.5,1144.59
PA2: CN4.21 R66.2 U18.22 | length 1682.4
  Top Layer w6: CN4.21@2493.11,-2.45 2540,44.44 2540,118.52 2449.6,208.92 2449.6,578.99 2208.01,820.58 2208.01,1013.71 2274.23,1079.92 U18.22@2320.76,1079.92 2558.82,1079.92 v2(2559.06,1080.17)
  Bottom Layer w6: v2(2559.06,1080.17) 2559.06,1039.74 2604.74,994.06 2613.53,994.06 R66.2@2625.5,982.09
PA3: CN4.26 R51.2 U18.25 | length 1274.4
  Top Layer w6: v2(2280.44,1001.61) 2282.36,1003.53 2282.36,1008.06 2295.17,1020.87 U18.25@2320.76,1020.87 2320.76,981.64 2356.8,945.6 2356.8,767.89 2468.2,656.49 2468.2,228.89 2556.2,140.89 2649.76,140.89 CN4.26@2693.11,97.55
  Bottom Layer w6: R51.2@2212.5,1057.5 2266.47,1003.53 2278.53,1003.53 v2(2280.44,1001.61)
PA4: CN4.25 R43.2 U18.26 | length 1316.2
  Top Layer w6: U18.26@2381.78,959.85 2381.77,775.26 2551.4,605.63 2551.4,233.99 2626.7,158.69 2692.2,158.69 2741.23,109.67 2741.23,45.67 CN4.25@2693.11,-2.45
  Bottom Layer w6: R43.2@2262.5,1057.5 2345,975 v2(2375,975)
PA5: CN4.28 U18.27 | length 1067.1
  Top Layer w6: U18.27@2401.46,959.85 2401.46,780.67 2564.4,617.73 2564.4,253.59 2642.3,175.69 2704.2,175.69 2782.35,97.55 CN4.28@2793.11,97.55
PA6: CN4.27 R46.2 R56.2 U18.28 | length 1337.3
  Top Layer w6: v2(2412.09,1026.5) 2412.09,1023.79 2421.15,1014.73 U18.28@2421.15,959.85 2421.15,786.08 2648,559.23 2648,260.49 2765.1,143.39 2805.6,143.39 2848.21,100.78 2848.21,52.65 CN4.27@2793.11,-2.45
  Bottom Layer w6: R46.2@2362.5,1057.5 R56.2@2412.5,1057.5 2412.09,1057.09 v2(2412.09,1026.5)
PA7: CN4.30 R47.2 R55.2 U18.29 | length 1332.4
  Top Layer w6: v2(2443.59,1026.04) 2441.94,1024.4 2441.94,960.97 U18.29@2440.83,959.85 2440.84,791.75 2666.1,566.49 2666.1,265.49 2771.5,160.09 2830.56,160.09 CN4.30@2893.11,97.55
  Bottom Layer w6: v2@2443.59,1026.09 R47.2@2475,1057.5 2443.75,1088.75 2443.75,1151.25 R55.2@2462.5,1170 ; R55.2@2463.8,1172.6 R55.2@2466,1170.4
PA8: CN5.32 CN8.6 R69.2 U18.69 | length 1416.9
  Top Layer w6: U18.69@2915.24,1375.2 v2(2990.01,1375.2) 3009.23,1375.2 3092.2,1458.17 3092.2,2126.96 3010.11,2209.05 CN8.6@3010.11,2216.55 3010.11,2381.9 3039.54,2411.34 3039.54,2489.11 CN5.32@2993.11,2535.55
  Bottom Layer w6: v2(2990.01,1375.2) 3044.89,1375.2 R69.2@3050.5,1369.59
PA9: CN5.31 CN8.2 JP3.3 U18.70 | length 3347.3
  Top Layer w6: v2(2862.81,1087.48) 2831.9,1118.39 2831.9,1344.6 2882.2,1394.89 U18.70@2915.24,1394.89 2970.42,1394.89 3001.57,1394.89 3077.89,1471.22 3077.89,2064.8 2968.01,2174.68 2968.01,2410.45 CN5.31@2993.11,2435.55
  Bottom Layer w6: v2(2862.81,1087.48) 2997.2,953.09 3167.8,953.09 3356.8,764.09 JP3.3@3968,764.09 ; CN5.31@2993.11,2435.55 3095.17,2333.48 3300.67,2333.48 3410.11,2224.05 CN8.2@3410.11,2216.55 CN8.2@3410.11,2209.05
PA10: CN5.30 CN8.1 JP3.4 U18.71 | length 3928.5
  Top Layer w6: v2(2852.06,1059.79) 2808.09,1103.76 2808.09,1347.26 2875.4,1414.57 U18.71@2915.24,1414.57 ; CN5.30@2893.11,2535.55 2950.66,2478 2950.66,2164.94 3063.59,2052.01 3063.59,1478.67 2999.49,1414.57 2934.18,1414.57 U18.71@2931.2,1411.59
  Bottom Layer w6: v2(2852.06,1059.79) 2972.26,939.59 3151.1,939.59 3384.5,706.19 4010.1,706.19 JP3.4@4068,764.09 ; CN5.30@2893.11,2535.55 2942.47,2486.19 3015.97,2486.19 3045.66,2456.5 3045.66,2412.1 3105.86,2351.91 3422.48,2351.91 3510.11,2264.29 CN8.1@3510.11,2216.55 CN8.1@3517.61,2209.05
PA11: CN5.29 CN8.7 R87.1 U18.72 | length 1215.3
  Top Layer w6: CN5.29@2893.11,2435.55 2901.1,2427.55 2901.1,2225.55 CN8.7@2910.11,2216.55 2910.11,2166.89 3049.28,2027.71 3049.28,1494.17 3006.11,1451 v2(3005.16,1451) 2987.4,1433.24 2919.94,1433.24 2917.08,1436.1 U18.72@2915.24,1434.26
  Bottom Layer w6: v2(3005.16,1451) 3044.09,1451 R87.1@3050.5,1444.59
PA12: CN5.28 CN8.8 R86.1 U18.73 | length 1335.7
  Top Layer w6: CN5.28@2793.11,2535.55 2840.2,2488.45 2840.2,2254.14 2810.11,2224.05 CN8.8@2810.11,2216.55 ; CN8.8@2811.1,2216.55 2811.1,2206.59 2810.32,2205.81 2811.1,2194.17 3034.98,1970.29 3034.98,1519.1 3006.63,1490.75 v2(3005.35,1490.75) 3005.35,1489.47 2969.83,1453.94 U18.73@2915.24,1453.94
  Bottom Layer w6: v2(3005.35,1490.75) 3046.65,1490.75 R86.1@3050.5,1494.59
PA13: CN5.25 R70.2 U18.76 | length 980.4
  Top Layer w6: CN5.25@2693.11,2435.55 2761.67,2366.98 2761.67,1938.32 2854.22,1845.77 2854.22,1619.59 U18.76@2854.22,1554.33
  Bottom Layer w6: v2(2855.5,1619.59) R70.2@2855.5,1652.09
PA14: CN5.24 R71.2 U18.77 | length 1145.1
  Top Layer w6: CN5.24@2593.11,2535.55 2640.7,2487.95 2640.7,2412.89 2734.6,2318.99 2734.6,1934.49 2834.54,1834.55 2834.54,1601.99 U18.77@2834.54,1554.33
  Bottom Layer w6: R71.2@2805.5,1652.09 2805.5,1628.79 2832.29,1601.99 v2(2835,1601.99)
PA15: CN5.23 CN6.3 R75.2 U18.78 | length 1286.2
  Top Layer w6: CN5.23@2593.11,2435.55 2700.9,2327.75 2700.9,2016.18 v6(2698.69,2013.96) 2698.69,1937.01 2814.85,1820.84 U18.78@2814.85,1554.33
  Bottom Layer w6: CN6.3@2450.11,2216.55 2593.11,2359.55 CN5.23@2593.11,2435.55 ; R75.2@2689.6,1984.69 2698.69,1993.78 v6(2698.69,2013.96)
PB0: CN4.31 R53.2 U18.32 | length 1501.2
  Top Layer w6: v2(2502.41,1005.53) 2501,1004.12 2501,960.97 U18.32@2499.89,959.85 2499.89,808.39 2852.87,455.41 2852.87,251.51 2964.3,140.07 3011.62,140.07 3047.3,104.39 3047.3,51.74 CN4.31@2993.11,-2.45
  Bottom Layer w6: R53.2@2310.4,1050.3 2318.41,1050.3 2324.21,1044.5 2324.21,1036.49 2355.17,1005.53 v2(2502.41,1005.53)
PB1: CN4.34 R52.2 U18.33 | length 1237.2
  Top Layer w6: v2(2524.89,1015.35) 2524.89,1012.65 2519.57,1007.33 2519.57,813.72 2871.83,461.46 2871.83,254.92 2967.52,159.23 3016.31,159.23 3077.99,97.55 CN4.34@3093.11,97.55
  Bottom Layer w6: v2(2524.89,1015.35) 2524.89,1057.39 R52.2@2525,1057.5
PB2: CN4.33 U18.34 | length 1296.9
  Top Layer w6: U18.34@2539.26,959.85 2536.51,957.1 2536.51,818.75 2888.72,466.54 2888.72,259.57 2975.69,172.59 3024.36,172.59 3055.53,141.42 3118.27,141.42 3138.5,121.19 3138.5,42.94 CN4.33@3093.11,-2.45
PB3: CN5.11 R44.2 R73.2 U18.90 | length 1384.1
  Top Layer w6: CN5.11@1993.11,2435.55 1993.11,2429.05 2090.6,2331.56 2090.6,2174.49 2578.63,1686.46 2578.63,1632.02 ; v7(2450.5,1482.1) 2474.25,1505.85 2561.45,1505.85 2577.52,1521.92 2577.52,1553.22 U18.90@2578.63,1554.33 ; U18.90@2578.63,1554.33 2578.61,1601.49 v7(2578.4,1601.7) 2578.61,1601.92 2578.61,1631.98
  Bottom Layer w6: R44.2@2450,1455 2450.5,1455.5 v7(2450.5,1482.1) ; v7(2578.4,1601.7) 2593,1616.3 R73.2@2593,1652.09
PB4: CN5.10 R76.2 U18.91 | length 1322.5
  Top Layer w6: CN5.10@1893.11,2535.55 1941.03,2487.63 1941.03,2414.03 2006.19,2348.87 2006.19,2189.21 2032.05,2163.34 2069.75,2163.34 2558.94,1674.15 2558.94,1616.47 U18.91@2558.94,1554.33
  Bottom Layer w6: R76.2@2543,1652.09 2544,1651.09 2544,1630.29 2557.82,1616.47 v7(2559.47,1616.47)
PB5: CN5.9 R81.2 U18.92 | length 1721.8
  Top Layer w6: R81.2@1710.5,1969.59 1729.5,1969.59 v6(1766.1,2006.19) ; CN5.9@1893.11,2435.55 1893.11,2423.6 1989.49,2327.21 1989.49,2179 2022.1,2146.4 ; 2022.1,2146.33 2056.7,2146.33 ; 2056.7,2146.4 2539.26,1663.83 U18.92@2539.26,1554.33
  Bottom Layer w6: v6(1766.1,2006.19) 1801.5,2041.59 1801.5,2343.94 CN5.9@1893.11,2435.55
PB6: CN5.8 R79.2 U18.93 | length 1975.4
  Top Layer w6: R79.2@1380.5,2152.09 1424.63,2152.09 v6(1425.23,2152.69) ; CN5.8@1793.11,2535.55 1800.55,2535.55 1842.1,2493.99 1842.1,2416.29 1897.73,2360.66 1897.73,2194.96 1963.37,2129.33 2042.77,2129.33 2519.57,1652.52 U18.93@2519.57,1554.33
  Bottom Layer w6: v6(1425.23,2152.69) 1487.5,2214.96 1487.5,2250.89 1561.3,2324.69 1667.4,2324.69 1747.3,2404.59 1747.3,2489.74 CN5.8@1793.11,2535.55
PB7: CN5.7 CN6.9 U18.94 | length 1224.5
  Top Layer w6: CN5.7@1793.11,2435.55 1793.11,2429.98 1850.11,2372.98 CN6.9@1850.11,2221.19 ; CN6.9@1850.11,2216.55 1850.11,2195.79 1933.57,2112.32 2027.77,2112.32 2499.89,1640.2 U18.94@2499.89,1554.33
PB8: CN5.6 CN6.10 R65.2 U18.95 | length 1919.2
  Top Layer w6: CN5.6@1693.11,2535.55 1744.29,2484.37 1744.29,2222.37 CN6.10@1750.11,2216.55 1871.34,2095.31 2013.78,2095.31 2480.2,1628.89 U18.95@2480.2,1554.33
  Bottom Layer w6: R65.2@1298,2032.09 1565.65,2032.09 CN6.10@1750.11,2216.55
PB9: CN5.5 U18.96 | length 1308.7
  Top Layer w6: CN5.5@1693.11,2435.55 1693.11,2433.79 1705.33,2421.56 1705.33,2185.56 1812.59,2078.31 1999.79,2078.31 2460.52,1617.57 U18.96@2460.52,1554.33
PB10: CN3.8 CN4.48 U18.47 | length 2396.9
  Top Layer w6: CN3.8@3625.12,1117.14 3575.56,1166.69 3366.28,1166.69 3183.69,984.1 2879.21,984.1 2853.15,1010.17 2809.12,1010.17 2795.17,996.21 U18.47@2795.17,959.85 2795.17,909.62 3255.2,449.6 3366.8,449.6 3470.4,345.99 3470.4,289.09 3510.9,248.59 3642.06,248.59 CN4.48@3793.11,97.55
PB11: CN4.49 R64.2 U18.50 | length 1716.2
  Top Layer w6: U18.50@2854.22,959.85 3013.84,959.85 3247.05,726.64 ; v2(3380.15,857.89) 3248.9,726.64 3247.05,726.64 ; CN4.49@3893.11,-2.45 3845.4,45.25 3845.4,128.29 3247.05,726.64
  Bottom Layer w6: v2(3380.15,857.89) 3408.35,886.09 R64.2@3411.05,886.09
PB12: CN3.7 CN5.50 R62.2 U18.51 | length 2336
  Top Layer w6: U18.51@2915.26,1020.85 3018.25,1020.85 v2(3018.52,1021.12) 3018.86,1020.78 3165.55,1020.78 3391.7,1246.93 3391.7,1847.71 3941.63,2397.65 3941.63,2487.02 CN5.50@3893.11,2535.55
  Bottom Layer w6: v2(3018.52,1021.12) 3022.74,1021.12 3046.21,1044.59 R62.2@3050.5,1044.59 ; v2(3391.4,1246.63) 3395.63,1246.63 CN3.7@3525.12,1117.14
PB13: CN3.3 CN5.49 R63.2 U18.52 | length 2204.8
  Top Layer w6: U18.52@2915.24,1040.55 2963.55,1040.55 2992.34,1040.55 3163.56,1040.55 3372.64,1249.63 3372.64,1316.04 v2(3372.4,1316.29) 3372.4,1851.43 3893.11,2372.14 CN5.49@3893.11,2435.55
  Bottom Layer w6: v2(2963.55,1040.76) 3009.72,994.59 R63.2@3050.5,994.59 ; v2(3372.4,1316.29) 3373.25,1317.14 CN3.3@3525.12,1317.14
PB14: CN3.1 CN5.48 U18.53 | length 2202.4
  Top Layer w6: U18.53@2915.24,1060.24 2955.74,1060.24 3160.65,1060.24 3347.49,1247.08 v2(3347.49,1414.92) 3346.8,1415.61 3346.8,1847.68 3842.1,2342.98 3842.1,2486.55 CN5.48@3793.11,2535.55
  Bottom Layer w6: v2(3347.49,1414.92) 3349.71,1417.14 CN3.1@3525.12,1417.14
PB15: CN3.4 CN5.47 U18.54 | length 2185.7
  Top Layer w6: U18.54@2915.24,1079.92 3159.93,1079.92 3322.7,1242.69 v2(3322.7,1364.89) 3321.6,1365.99 3321.6,1848.01 3793.11,2319.52 CN5.47@3793.11,2435.55
  Bottom Layer w6: v2(3322.7,1364.89) 3323,1364.59 3577.66,1364.59 CN3.4@3625.12,1317.14
PC0: CN4.16 R95.1 U18.15 | length 1625.1
  Top Layer w6: CN4.16@2193.11,97.55 2055.5,235.15 2055.5,999.04 2274.18,1217.72 U18.15@2320.76,1217.72 2588.09,1217.72 v2(2588.14,1217.67)
  Bottom Layer w6: v2(2588.14,1217.67) 2590.18,1219.71 2613.11,1219.71 R95.1@2625.5,1232.09
PC1: CN4.15 R61.2 R94.1 U18.16 | length 1757.7
  Top Layer w6: CN4.15@2193.11,-2.45 2240.2,44.64 2240.2,110.39 2148.8,201.79 2148.8,714.19 2103.59,759.4 2103.59,1027.38 2274.26,1198.04 U18.16@2320.76,1198.03 ; U18.16@2320.76,1198.03 2583.01,1198.01 v2(2589.05,1191.98)
  Bottom Layer w6: v2(2589.05,1191.98) 2592.21,1195.14 2612.45,1195.14 R94.1@2625.5,1182.09 R61.2@2625.5,1132.09
PC2: CN4.18 R92.1 U18.17 | length 1641.8
  Top Layer w6: CN4.18@2293.11,97.55 2166.5,224.15 2166.5,724.69 2120.99,770.2 2120.99,1025.59 2273.76,1178.35 U18.17@2320.76,1178.35 2321.34,1178.93 2558.6,1178.93 v2(2559.17,1179.51)
  Bottom Layer w6: v2(2559.17,1179.51) 2559.17,1233.66 2594.61,1269.09 2612.5,1269.09 R92.1@2625.5,1282.09
PC3: CN4.17 R96.1 U18.18 | length 1402.2
  Top Layer w6: CN4.17@2293.11,-2.45 2339.1,43.54 2339.1,118.09 2248.3,208.89 2248.3,673.69 v2(2218.1,703.89) 2138.4,783.6 2138.4,1024.89 2272.18,1158.67 U18.18@2320.76,1158.66
  Bottom Layer w6: R96.1@2184.2,706.19 2186.5,703.89 v2(2218.1,703.89)
PC4: CN4.29 R59.2 U18.30 | length 1464.8
  Top Layer w6: U18.30@2460.52,987.02 2460.52,797.16 2749.5,508.18 2749.5,236.09 2808.3,177.29 2875.9,177.29 2940.3,112.89 2940.3,44.74 CN4.29@2893.11,-2.45 ; U18.30@2460.79,987.28 2460.79,1018.89 2492.87,1050.97 2579.02,1050.97 v2(2579.73,1050.27)
  Bottom Layer w6: v2(2579.73,1050.27) 2582.44,1050.27 2588,1044.7 2612.89,1044.7 R59.2@2625.5,1032.09
PC5: CN4.32 R60.2 U18.31 | length 1358.6
  Top Layer w6: v2(2599.4,1069.7) 2599.4,1044.8 2586.95,1032.35 2498.55,1032.35 2481.29,1015.09 2481.29,960.95 U18.31@2480.2,959.85 2480.2,802.8 2766.8,516.2 2766.8,252.89 2826.77,192.92 2886.97,192.92 2982.35,97.55 CN4.32@2993.11,97.55
  Bottom Layer w6: v2(2599.4,1069.7) 2613.11,1069.7 R60.2@2625.5,1082.09
PC6: CN5.36 CN8.3 U18.65 | length 1523.3
  Top Layer w6: U18.65@2915.24,1296.46 3038.41,1296.46 3149.41,1407.46 3149.41,2046.61 3310.11,2207.3 CN8.3@3310.11,2216.55 3242.66,2284 3242.66,2486 CN5.36@3193.11,2535.55
PC7: CN5.35 CN8.4 U18.66 | length 1313.6
  Top Layer w6: U18.66@2915.24,1316.15 3025.71,1316.15 3135.11,1425.55 3135.11,2098.53 3210.5,2173.92 3210.5,2406.29 3193.11,2423.69 CN5.35@3193.11,2435.55
PC8: CN5.34 R68.2 U18.67 | length 1460.2
  Top Layer w6: U18.67@2915.24,1335.83 3020.54,1335.83 3120.81,1436.1 3120.81,2145.7 3159.31,2184.2 3159.31,2373.89 3140.1,2393.09 3140.1,2488.55 CN5.34@3093.11,2535.55
  Bottom Layer w6: v2(2987.1,1336.19) 3003.7,1319.59 R68.2@3050.5,1319.59
PC9: CN5.33 CN8.5 U18.68 | length 1217.9
  Top Layer w6: U18.68@2915.24,1355.52 3015.35,1355.52 3106.5,1446.68 CN8.5@3106.5,2216.55 ; CN8.5@3093.11,2216.55 CN5.33@3093.11,2435.55
PC10: CN5.22 CN6.6 R80.2 U18.79 | length 2170.7
  Top Layer w6: CN5.22@2493.11,2535.55 2546.7,2481.95 2546.7,2402.99 2607.2,2342.49 2607.2,1999.89 2795.17,1811.92 U18.79@2795.17,1554.33
  Bottom Layer w6: R80.2@1710.5,1969.59 1711.1,1970.19 1903.75,1970.19 CN6.6@2150.11,2216.55 2150.11,2226 2270.7,2346.59 2375.5,2346.59 2444.3,2415.39 2444.3,2486.74 CN5.22@2493.11,2535.55
PC11: CN5.21 CN6.5 U18.80 | length 1380.7
  Top Layer w6: CN5.21@2493.11,2435.55 2590.4,2338.25 2590.4,1985.69 2775.48,1800.61 U18.80@2775.48,1554.33
  Bottom Layer w6: CN6.5@2250.11,2216.55 2250.11,2299.9 2278.7,2328.49 2386.05,2328.49 CN5.21@2493.11,2435.55
PC12: CN5.20 CN6.4 U18.81 | length 1319.7
  Top Layer w6: CN5.20@2393.11,2535.55 2442.9,2485.75 2442.9,2423.99 2509.32,2357.58 2509.32,2163.11 v2(2511.09,2161.35) 2511.82,2160.61 2511.82,2033.27 2755.8,1789.29 U18.81@2755.8,1554.33
  Bottom Layer w6: CN6.4@2350.11,2216.55 2350.11,2209.05 2397.81,2161.35 v2(2511.09,2161.35)
PC13: CN4.8 U18.7 | length 2044.9
  Top Layer w6: CN4.8@1793.11,97.55 1756.12,134.53 1756.12,1466.7 1826.01,1536.59 2119.97,1536.59 2281.36,1375.2 U18.7@2320.76,1375.2
PC14: CN4.7 R37.1 | length 1569.6
  Bottom Layer w6: CN4.7@1793.11,-2.45 1846.6,51.04 1846.6,135.09 1902.66,191.15 1902.66,1259.45 1969.4,1326.2 1969.4,1412 2001.99,1444.59 R37.1@2038,1444.59
PC15: CN4.10 R38.1 | length 1373.2
  Bottom Layer w6: CN4.10@1893.11,97.55 1893.11,100.06 1918.41,125.37 1918.41,1242.81 1989.3,1313.69 1989.3,1377.69 2006.2,1394.59 R38.1@2035.5,1394.59
PD0: CN5.19 CN6.1 U18.82 | length 1240.6
  Top Layer w6: CN5.19@2393.11,2435.55 2489.9,2338.75 v2(2489.9,2099.31) 2488.41,2097.83 2488.41,2024.68 2736.11,1776.98 U18.82@2736.11,1554.33
  Bottom Layer w6: v2(2489.9,2099.31) 2490.31,2098.9 2544.4,2098.9 2625.61,2180.1 2625.61,2192.05 CN6.1@2650.11,2216.55
PD1: CN5.18 CN6.2 U18.83 | length 1370.1
  Top Layer w6: CN5.18@2293.11,2535.55 2346.5,2482.15 2346.5,2411.59 2407.16,2350.93 v2(2407.16,2124.56) 2407.1,2124.5 2407.1,2075.3 2716.43,1765.97 U18.83@2716.43,1554.33
  Bottom Layer w6: v2(2407.16,2124.56) 2513.57,2124.56 2550.11,2161.1 CN6.2@2550.11,2216.55
PD2: CN5.17 R50.2 U18.84 | length 1323.1
  Top Layer w6: CN5.17@2293.11,2435.55 2388.5,2340.15 2388.5,2062.59 2696.74,1754.35 2696.74,1519.51 2660.39,1483.16 v7(2500.17,1483.16)
  Bottom Layer w6: R50.2@2500,1455 2500.17,1455.17 v7(2500.17,1483.16)
PD3: CN5.16 U18.85 | length 1181.7
  Top Layer w6: CN5.16@2193.11,2535.55 2241.4,2487.25 2241.4,2426.49 2308.2,2359.69 2308.2,2111.89 2677.06,1743.03 U18.85@2677.06,1554.33
PD4: CN5.15 U18.86 | length 1073.5
  Top Layer w6: CN5.15@2193.11,2435.55 2289.6,2339.05 2289.6,2099.49 2657.37,1731.72 U18.86@2657.37,1554.33
PD5: CN5.14 U18.87 | length 1206.8
  Top Layer w6: CN5.14@2093.11,2535.55 2141.3,2487.35 2141.3,2421.59 2210.5,2352.39 2210.5,2147.59 2637.69,1720.4 U18.87@2637.69,1554.33
PD6: CN5.13 U18.88 | length 1098.6
  Top Layer w6: CN5.13@2093.11,2435.55 2194.5,2334.15 2194.5,2131.59 2618,1708.09 U18.88@2618,1554.33
PD7: CN5.12 U18.89 | length 1232.7
  Top Layer w6: CN5.12@1993.11,2535.55 2043.37,2485.28 2043.37,2414.47 2107.9,2349.94 2107.9,2187.81 2598.32,1697.39 U18.89@2598.32,1554.33 U18.89@2597.74,1553.76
